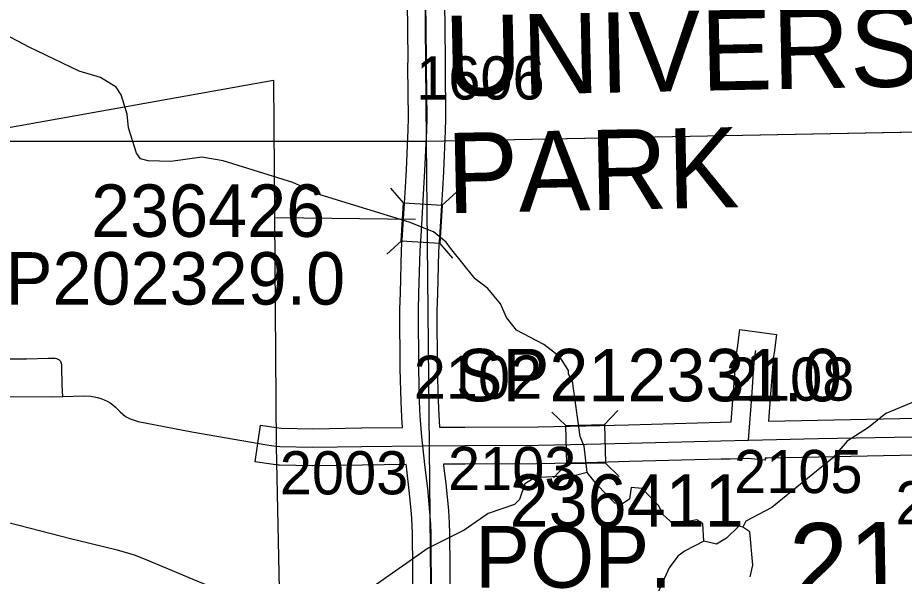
# Model space of a CAD drawing. Extents: x 23.6 to 68.7, y -63 to -29.
# Drawn here: x 46.003 to 47.439, y -49.268 to -48.362 of the extents above; entities that cross this region are included whole.
import ezdxf

# ---------------------------------------------------------------- set-up
doc = ezdxf.new("R2010")
doc.units = 0
for name, color, linetype in [('tdCoCityStreetMajor', 7, 'Continuous'), ('tdCoCityStreetMinor', 7, 'Continuous'), ('tdCoCorpBndry', 7, 'Continuous'), ('tdCoCorpPopTxt', 7, 'Continuous'), ('tdCoCorpTxt', 7, 'Continuous'), ('tdCoHydroRiver', 7, 'Continuous'), ('tdCoSecRdNmbr', 7, 'Continuous'), ('tdCoSecRteBand', 7, 'Continuous'), ('tdCoSecRteCL', 7, 'Continuous'), ('tdCoSectLine', 7, 'Continuous'), ('tdCoSectLinePart', 7, 'Continuous'), ('tdCoSectNmbr', 7, 'Continuous'), ('tdCoStrucSec', 7, 'Continuous'), ('tdCoStrucSecCoName', 7, 'Continuous'), ('tdCoStrucSecFHWANum', 7, 'Continuous'), ('tdCoSurfConc', 7, 'Continuous'), ('tdCoSurfConcUnbanded', 7, 'Continuous'), ('tdCoSurfGravel', 7, 'Continuous'), ('tdCoSurfGravelUnbanded', 7, 'Continuous')]:
    doc.layers.add(name, color=color, linetype=linetype)

msp = doc.modelspace()

# ---------------------------------------------------------------- linework, layer by layer
at = {"layer": 'tdCoCityStreetMajor'}
msp.add_lwpolyline([(45.9571, -48.9764), (46.0582, -48.9769), (46.0757, -48.9765), (46.1097, -48.9756), (46.1213, -48.9761), (46.1268, -48.9769), (46.1322, -48.9781), (46.1375, -48.9797), (46.1426, -48.9817), (46.1476, -48.9841), (46.1524, -48.9869), (46.1569, -48.9901), (46.1612, -48.9936), (46.1652, -48.9974), (46.1689, -49.0015), (46.1773, -49.0089), (46.1852, -49.0128), (46.1977, -49.017), (46.285, -49.0338), (46.4066, -49.0548), (46.4216, -49.0569)], dxfattribs=at)
at = {"layer": 'tdCoCityStreetMinor'}
for points in [[(45.9268, -48.9152), (45.9477, -48.9152), (46.0168, -48.9151), (46.0522, -48.9144), (46.0612, -48.9144), (46.0635, -48.9144), (46.0658, -48.9148), (46.068, -48.9157), (46.0699, -48.917), (46.0716, -48.9186), (46.0729, -48.9205)], [(46.0757, -48.9765), (46.0749, -48.9582), (46.0744, -48.9272), (46.0743, -48.9249), (46.0738, -48.9226), (46.0729, -48.9205)]]:
    msp.add_lwpolyline(points, dxfattribs=at)
at = {"layer": 'tdCoCorpBndry'}
msp.add_lwpolyline([(46.4173, -48.4633), (46.4216, -49.0567), (46.4274, -49.3397), (46.4283, -49.3779), (46.4324, -49.564), (45.6798, -49.5692), (45.6676, -48.5718), (45.7661, -48.5707), (45.924, -48.5514)], close=True, dxfattribs=at)
at = {"layer": 'tdCoHydroRiver'}
for points in [[(46.9254, -49.0995), (46.9202, -49.057), (46.9137, -49.0413), (46.9017, -48.9514), (46.8952, -48.9404), (46.8951, -48.9341), (46.8807, -48.9122), (46.8552, -48.8919), (46.8108, -48.8687), (46.7948, -48.8484), (46.7851, -48.8264), (46.7643, -48.8014), (46.7436, -48.7858), (46.7036, -48.7357), (46.6971, -48.7263), (46.6764, -48.7092), (46.6368, -48.6938), (46.4927, -48.6496), (46.4482, -48.6296), (46.3358, -48.5945), (46.301, -48.5886), (46.2506, -48.5955), (46.2142, -48.5943), (46.2016, -48.5913), (46.1952, -48.5819), (46.1821, -48.541), (46.1803, -48.5189), (46.1704, -48.4874), (46.1624, -48.4749), (46.137, -48.4594), (46.1021, -48.4487), (46.0212, -48.4101), (45.9498, -48.373)], [(47.4561, -48.9848), (47.4089, -49.0042), (47.3808, -49.0267), (47.3463, -49.0491), (47.3229, -49.0762), (47.2243, -49.1562), (47.182, -49.1788), (47.1773, -49.1883)], [(46.9254, -49.0995), (46.9065, -49.1045), (46.8402, -49.1084), (46.8245, -49.118), (46.8154, -49.1434), (46.8075, -49.1513), (46.7651, -49.166), (46.7259, -49.1933), (46.6678, -49.2223), (46.5738, -49.2881), (46.5238, -49.3297), (46.4705, -49.3666), (46.4485, -49.3763), (46.3823, -49.3833), (46.3412, -49.3774), (46.1438, -49.3701), (46.0933, -49.3691), (46.0602, -49.3789), (46.0069, -49.4111), (45.9818, -49.4209), (45.9157, -49.4405)], [(47.1144, -49.2111), (47.1125, -49.1827), (47.103, -49.1765), (47.0652, -49.1832), (47.0477, -49.1676), (47.0412, -49.1535), (47.0141, -49.1254), (46.9967, -49.124), (46.9937, -49.143), (46.9812, -49.151), (46.9701, -49.1496), (46.9414, -49.1199), (46.9254, -49.0995)], [(47.1773, -49.1883), (47.171, -49.1868), (47.1507, -49.206), (47.135, -49.2156), (47.1144, -49.2111)], [(47.1893, -49.2687), (47.1938, -49.2497), (47.1885, -49.1961), (47.1773, -49.1883)], [(47.1144, -49.2111), (47.083, -49.2272), (47.0721, -49.2353), (47.0581, -49.2543), (47.0365, -49.3019), (47.0304, -49.3225), (47.0278, -49.3683), (47.0326, -49.3809), (47.0444, -49.4502), (47.0452, -49.5244), (47.0516, -49.5275), (47.0537, -49.5748), (47.0651, -49.6095), (47.0688, -49.6599), (47.0885, -49.7276), (47.084, -49.7482), (47.0545, -49.7958), (47.0342, -49.8134)]]:
    msp.add_lwpolyline(points, dxfattribs=at)
at = {"layer": 'tdCoSecRteBand'}
for points in [[(46.6433, -49.3074), (46.6425, -49.1999), (46.6419, -49.1851), (46.6406, -49.1664), (46.6371, -49.1288), (46.633, -49.0955), (46.633, -49.0953), (46.633, -49.0951), (46.6324, -49.0897), (46.6321, -49.0868), (46.5606, -49.0875), (46.4811, -49.0887), (46.4805, -49.0887), (46.48, -49.0887), (46.427, -49.0877), (46.4252, -49.0877), (46.4234, -49.0874), (46.4174, -49.0866), (46.3877, -49.0824), (46.3961, -49.023), (46.4258, -49.0272), (46.43, -49.0278), (46.4806, -49.0287), (46.5598, -49.0275), (46.5599, -49.0275), (46.56, -49.0275), (46.6261, -49.0269), (46.6248, -49.0107), (46.6248, -49.0101), (46.6248, -49.0096), (46.6238, -48.9856), (46.6238, -48.9853), (46.6238, -48.9851), (46.6225, -48.9318), (46.6225, -48.9315), (46.6225, -48.9313), (46.6218, -48.8367), (46.6218, -48.8362), (46.6218, -48.8356), (46.6226, -48.8082), (46.6246, -48.7393), (46.6246, -48.7388), (46.6247, -48.7382), (46.6268, -48.7061), (46.6309, -48.637), (46.6325, -48.609), (46.6353, -48.5435), (46.6358, -48.5251), (46.635, -48.4414), (46.6349, -48.4411), (46.635, -48.4407), (46.6351, -48.4296), (46.634, -48.3362)], [(46.694, -48.3354), (46.6951, -48.4293), (46.6951, -48.4297), (46.6951, -48.4301), (46.695, -48.4412), (46.6958, -48.525), (46.6958, -48.5255), (46.6958, -48.5261), (46.6953, -48.5453), (46.6953, -48.5456), (46.6953, -48.5458), (46.6925, -48.6117), (46.6924, -48.612), (46.6924, -48.6122), (46.6908, -48.6405), (46.6908, -48.6405), (46.6908, -48.6405), (46.6867, -48.7097), (46.6867, -48.7098), (46.6867, -48.7099), (46.6846, -48.7416), (46.6826, -48.8099), (46.6826, -48.8099), (46.6826, -48.81), (46.6818, -48.8369), (46.6825, -48.9306), (46.6838, -48.9833), (46.6847, -49.0065), (46.6863, -49.0264)], [(46.6863, -49.0264), (46.7269, -49.026), (46.727, -49.026), (46.7271, -49.026), (46.8459, -49.0255), (46.9233, -49.0238), (46.9923, -49.0221), (47.141, -49.0181), (47.141, -49.0181), (47.1411, -49.0181), (47.1587, -49.0177), (47.162, -48.9752), (47.1654, -48.9263), (47.1654, -48.9259), (47.1655, -48.9256), (47.1671, -48.908), (47.1672, -48.9073), (47.1673, -48.9065), (47.1686, -48.8973), (47.1728, -48.8676), (47.2322, -48.8761), (47.228, -48.9058), (47.2268, -48.9143), (47.2252, -48.9308), (47.2218, -48.9795), (47.2218, -48.9795), (47.2218, -48.9796), (47.219, -49.0164), (47.2989, -49.0147), (47.299, -49.0147), (47.299, -49.0147), (47.4848, -49.0111)], [(47.484, -49.0711), (47.3002, -49.0747), (47.2171, -49.0765), (47.2138, -49.0765), (47.2135, -49.0798), (47.1854, -49.0772), (47.1571, -49.0778), (47.1425, -49.0781), (46.9938, -49.082), (46.9938, -49.082), (46.9938, -49.082), (46.9247, -49.0838), (46.9247, -49.0838), (46.9247, -49.0838), (46.847, -49.0855), (46.8467, -49.0855), (46.8464, -49.0855), (46.7274, -49.086), (46.6924, -49.0863), (46.6926, -49.0884), (46.6967, -49.1219), (46.6968, -49.1223), (46.6968, -49.1227), (46.7004, -49.1612), (46.7004, -49.1616), (46.7005, -49.162), (46.7018, -49.1814), (46.7018, -49.1818), (46.7018, -49.1822), (46.7025, -49.198), (46.7025, -49.1985), (46.7025, -49.199), (46.7033, -49.3069)]]:
    msp.add_lwpolyline(points, dxfattribs=at)
at = {"layer": 'tdCoSecRteCL'}
for points in [[(46.659, -49.0566), (46.6574, -49.0419), (46.6548, -49.0083), (46.6538, -48.9843), (46.6525, -48.9311), (46.6518, -48.8365), (46.6526, -48.8091), (46.6546, -48.7402), (46.6567, -48.708), (46.6608, -48.6387), (46.6625, -48.6105), (46.6653, -48.5445), (46.6658, -48.5253), (46.665, -48.4411), (46.6651, -48.4296), (46.664, -48.3357), (46.6636, -48.3116), (46.6631, -48.283), (46.6623, -48.2287), (46.6618, -48.1283), (46.661, -48.0365), (46.6599, -47.9458), (46.6589, -47.8503), (46.6585, -47.8039)], [(47.1865, -49.0471), (47.1871, -49.0403), (47.1919, -48.9774), (47.1953, -48.9284), (47.197, -48.9108), (47.1983, -48.9016)], [(47.1865, -49.0471), (47.2996, -49.0447), (47.5153, -49.0405)], [(46.659, -49.0566), (46.7272, -49.056), (46.8463, -49.0555), (46.924, -49.0538), (46.993, -49.0521), (47.1417, -49.0481), (47.1865, -49.0471)], [(46.4216, -49.0569), (46.4276, -49.0577), (46.4806, -49.0587), (46.5603, -49.0575), (46.659, -49.0566)], [(46.6751, -49.4632), (46.675, -49.4369), (46.6745, -49.3814), (46.6733, -49.3072), (46.6725, -49.1992), (46.6719, -49.1834), (46.6705, -49.164), (46.6669, -49.1255), (46.6628, -49.0918), (46.659, -49.0566)], [(45.9515, -49.1717), (46.0904, -49.2072), (46.0996, -49.2095), (46.1641, -49.2252), (46.1912, -49.2331), (46.2095, -49.24), (46.2862, -49.2728), (46.3868, -49.314), (46.4035, -49.3214), (46.4141, -49.3278), (46.4233, -49.3349), (46.4274, -49.3397), (46.4381, -49.352), (46.4506, -49.3658), (46.4659, -49.3771), (46.4894, -49.3887), (46.5261, -49.4042), (46.661, -49.4578), (46.6751, -49.4632)]]:
    msp.add_lwpolyline(points, dxfattribs=at)
at = {"layer": 'tdCoSectLine'}
for points in [[(46.6558, -47.5574), (46.6642, -48.5626)], [(46.6642, -48.5626), (47.6616, -48.5433)], [(45.6767, -48.5622), (46.6642, -48.5626)], [(46.6642, -48.5626), (46.6744, -49.5566)]]:
    msp.add_lwpolyline(points, dxfattribs=at)
at = {"layer": 'tdCoSectLinePart'}
for points in [[(46.694, -48.562), (47.6311, -48.5439)], [(46.4177, -48.5625), (46.634, -48.5626)]]:
    msp.add_lwpolyline(points, dxfattribs=at)
at = {"layer": 'tdCoStrucSec'}
for p, q in [((46.6277, -48.6623), (46.607, -48.6389)), ((46.6902, -48.666), (46.7136, -48.6452)), ((46.624, -48.7248), (46.6006, -48.7456)), ((46.6865, -48.7285), (46.7073, -48.7519)), ((46.9532, -49.0217), (46.9747, -48.9991)), ((46.8906, -49.0233), (46.8679, -49.0017)), ((46.9547, -49.0843), (46.9773, -49.1059)), ((46.8921, -49.0858), (46.8705, -49.1085))]:
    msp.add_line(p, q, dxfattribs=at)
for points in [[(46.624, -48.7248), (46.6277, -48.6623), (46.6902, -48.666), (46.6865, -48.7285)], [(46.8906, -49.0233), (46.9532, -49.0217), (46.9547, -49.0843), (46.8921, -49.0858)]]:
    msp.add_lwpolyline(points, close=True, dxfattribs=at)
at = {"layer": 'tdCoStrucSecFHWANum'}
msp.add_line((46.421, -48.686), (46.6473, -48.6891), dxfattribs=at)
at = {"layer": 'tdCoSurfConc'}
msp.add_lwpolyline([(46.6733, -49.3072), (46.6725, -49.1992), (46.6719, -49.1834), (46.6705, -49.164), (46.6669, -49.1255), (46.6628, -49.0918), (46.659, -49.0566), (46.6574, -49.0419), (46.6548, -49.0083), (46.6538, -48.9843), (46.6525, -48.9311), (46.6518, -48.8365), (46.6526, -48.8091), (46.6546, -48.7402), (46.6567, -48.708), (46.6608, -48.6387), (46.6625, -48.6105), (46.6653, -48.5445), (46.6658, -48.5253), (46.665, -48.4411), (46.6651, -48.4296), (46.664, -48.3357), (46.6636, -48.3116)], dxfattribs=at)
at = {"layer": 'tdCoSurfConcUnbanded'}
msp.add_lwpolyline([(45.6739, -49.0897), (45.6911, -49.0957), (45.7047, -49.1006), (45.7663, -49.1226), (45.7761, -49.1262), (45.8105, -49.1386), (45.8435, -49.1478), (45.8524, -49.1502), (45.9286, -49.1667), (45.9515, -49.1717), (46.0904, -49.2072), (46.0996, -49.2095)], dxfattribs=at)
at = {"layer": 'tdCoSurfGravel'}
for points in [[(47.1865, -49.0471), (47.1871, -49.0403), (47.1919, -48.9774), (47.1953, -48.9284), (47.197, -48.9108), (47.1983, -48.9016)], [(46.4216, -49.0569), (46.4276, -49.0577), (46.4806, -49.0587), (46.5603, -49.0575), (46.659, -49.0566), (46.7272, -49.056), (46.8463, -49.0555), (46.924, -49.0538), (46.993, -49.0521), (47.1417, -49.0481), (47.1865, -49.0471), (47.2996, -49.0447), (47.5153, -49.0405), (47.5437, -49.04), (47.6705, -49.039)]]:
    msp.add_lwpolyline(points, dxfattribs=at)
at = {"layer": 'tdCoSurfGravelUnbanded'}
msp.add_lwpolyline([(46.0996, -49.2095), (46.1641, -49.2252), (46.1912, -49.2331), (46.2095, -49.24), (46.2862, -49.2728), (46.3868, -49.314), (46.4035, -49.3214), (46.4141, -49.3278), (46.4233, -49.3349), (46.4274, -49.3397)], dxfattribs=at)

# ---------------------------------------------------------------- texts
at = {"layer": 'tdCoCorpPopTxt'}
msp.add_text('POP.', height=0.1, dxfattribs=at).set_placement((46.7435, -49.2864))
at = {"layer": 'tdCoCorpTxt'}
for s, p in [('UNIVERSITY', (46.6951, -48.4894)), ('PARK', (46.6991, -48.6793))]:
    msp.add_text(s, height=0.13, rotation=1.2, dxfattribs=at).set_placement(p)
at = {"layer": 'tdCoSecRdNmbr'}
for s, rotation, p in [('1606', 0.0363, (46.6482, -48.495)), ('2102', 0.0363, (46.6442, -48.9802)), ('2108', 0.0367, (47.1498, -48.9833)), ('2003', 0.0362, (46.4273, -49.1352)), ('2103', 0.0364, (46.6998, -49.1281)), ('2105', 0.0367, (47.1631, -49.1331)), ('2110', 0.0369, (47.4245, -49.1838))]:
    msp.add_text(s, height=0.07, rotation=rotation, dxfattribs=at).set_placement(p)
at = {"layer": 'tdCoSectNmbr'}
msp.add_text('21', height=0.13, rotation=1.0367, dxfattribs=at).set_placement((47.2533, -49.3126))
at = {"layer": 'tdCoStrucSecCoName'}
for s, p in [('SP202329.0', (45.9075, -48.8274)), ('SP212331.0', (46.7123, -48.9842))]:
    msp.add_text(s, height=0.085, dxfattribs=at).set_placement(p)
at = {"layer": 'tdCoStrucSecFHWANum'}
for s, p in [('236426', (46.1216, -48.7176)), ('236411', (46.7995, -49.1877))]:
    msp.add_text(s, height=0.085, dxfattribs=at).set_placement(p)

doc.saveas('drawing.dxf')
